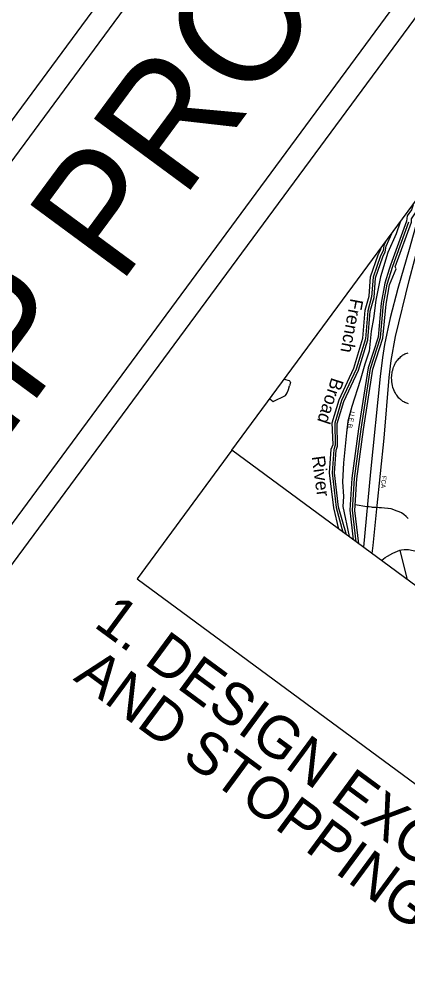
# Model space of a CAD drawing. Extents: x 945666 to 965748, y 644452 to 663300.
# Drawn here: x 951483 to 952293, y 657713 to 659710 of the extents above; entities that cross this region are included whole.
import ezdxf

# ---------------------------------------------------------------- set-up
doc = ezdxf.new("R2010")
doc.units = 0
for name, color, linetype in [('Exist Boundary Political Urban Extension UEB', 7, 'Continuous'), ('Exist Boundary Political Urban Extension UEB Label', 7, 'Continuous'), ('Exist Hydrographic Buffer Line', 7, 'Continuous'), ('Exist Hydrographic Creek Single Shore', 7, 'Continuous'), ('Exist Hydrographic Pond Under 1500 Sq Ft', 7, 'Continuous'), ('Exist Hydrographic River Shore', 7, 'Continuous'), ('Exist Hydrographic River Shore Label', 7, 'Continuous'), ('Exist Road Primary Interstate Divided Center Attributed', 7, 'Continuous'), ('Exist Road Primary US Label', 7, 'Continuous'), ('Exist Road Secondary Type 51 Attributed', 7, 'Continuous'), ('Old_Level_1', 7, 'Continuous'), ('Prop Terminator CELL', 7, 'Continuous'), ('Sheet Data Field CELL', 7, 'Continuous'), ('Sheet Title CELL', 7, 'Continuous')]:
    doc.layers.add(name, color=color, linetype=linetype)

msp = doc.modelspace()

# ---------------------------------------------------------------- linework, layer by layer
at = {"layer": 'Exist Boundary Political Urban Extension UEB'}
msp.add_lwpolyline([(952276.6, 659287.1), (952268.7, 659263.3), (952251.1, 659224.5), (952236, 659173.2), (952226.3, 659124.6), (952221.3, 659086.9), (952216.4, 659060.2), (952212.4, 659018.3), (952202.9, 658991.5), (952193.4, 658957.2), (952176.2, 658903), (952167.9, 658872.6), (952165.2, 658848.4), (952158.8, 658785.6), (952156.8, 658746.4), (952158.7, 658715.4), (952157.4, 658694.7), (952170.3, 658632.2), (952170.3, 658632.1)], dxfattribs=at)
at = {"layer": 'Exist Hydrographic Buffer Line'}
for points in [[(952303.7, 659323.8), (952300.7, 659313.2), (952291.7, 659300.3), (952289.8, 659289.2), (952256.4, 659197.7), (952253.9, 659189.6), (952244.7, 659160.5), (952237.2, 659118.3), (952230.7, 659047.9), (952209.9, 658984.1), (952190.2, 658857), (952176.2, 658754.1), (952172.3, 658687.5), (952179.2, 658625.5)], [(952184.9, 658621.3), (952177.4, 658687.2), (952181.4, 658753.4), (952195.3, 658856.2), (952214.9, 658982.5), (952235.9, 659046.8), (952242.4, 659117.5), (952249.5, 659158.5), (952261.3, 659195.9), (952295, 659288.3)], [(952165.2, 658635.9), (952148.5, 658693.8), (952140.1, 658764.9), (952143.6, 658812.4), (952146.6, 658820.6), (952145.9, 658868), (952159.7, 658913.6), (952189.8, 658979), (952209.3, 659042.5), (952214.4, 659101.9), (952222.4, 659130.5), (952225.6, 659171.5), (952240.6, 659215.4), (952245.9, 659225.3), (952248, 659237.5), (952259.5, 659264)], [(952245.7, 659245.3), (952242.9, 659238.8), (952241.4, 659227.8), (952235.8, 659217.4), (952220.5, 659172.5), (952217.4, 659132), (952209.2, 659102.8), (952204.3, 659044), (952185, 658981.1), (952154.9, 658915.5), (952140.7, 658868.7), (952141.7, 658822.4), (952138.5, 658813.5), (952134.9, 658764.8), (952143.4, 658692.9), (952157.7, 658641.4)]]:
    msp.add_lwpolyline(points, dxfattribs=at)
at = {"layer": 'Exist Hydrographic Creek Single Shore'}
msp.add_lwpolyline([(952293.8, 658669.9), (952289.3, 658674.2), (952284.5, 658677.9), (952279.7, 658681.4), (952274.5, 658683.6), (952268.8, 658686.1), (952263.6, 658688.2), (952257.8, 658689.8), (952251.5, 658690.6), (952250.9, 658690.7), (952244.5, 658691.5), (952237.8, 658691.8), (952232.8, 658691.8), (952226.3, 658692.8), (952223.3, 658692.7), (952219.5, 658693), (952217, 658693.5), (952212.4, 658694.2), (952207.4, 658694.4), (952183.3, 658698.2)], dxfattribs=at)
at = {"layer": 'Exist Hydrographic Pond Under 1500 Sq Ft'}
for points in [[(952005.2, 658919.1), (952005.5, 658918.9), (952012.1, 658913.4), (952037.7, 658926.4), (952039.6, 658928.4), (952041.7, 658931.5), (952042.1, 658932.9), (952044.1, 658938.6), (952046.4, 658946.6)], [(952035.3, 658959.9), (952045.6, 658957.7), (952047.3, 658956.2), (952048.5, 658953.4), (952046.4, 658946.6)]]:
    msp.add_lwpolyline(points, dxfattribs=at)
at = {"layer": 'Exist Hydrographic River Shore'}
for points in [[(952190.6, 658617.1), (952182.6, 658686.9), (952186.5, 658752.7), (952200.4, 658855.5), (952219.8, 658980.9), (952241, 659045.8), (952247.5, 659116.6), (952254.3, 659156.5), (952268.3, 659189.8), (952266.2, 659194.1), (952300.2, 659287.4), (952300.2, 659294.3), (952310.2, 659308.7), (952320.5, 659346), (952321.5, 659348.1)], [(952149, 658647.8), (952138.3, 658691.9), (952129.7, 658764.7), (952133.3, 658814.6), (952136.9, 658824.2), (952135.5, 658869.4), (952150, 658917.3), (952180.3, 658983.3), (952199.3, 659045.5), (952204.1, 659103.7), (952212.4, 659133.4), (952215.3, 659173.6), (952231.1, 659219.5), (952236.8, 659230.2), (952237.1, 659233.7)]]:
    msp.add_lwpolyline(points, dxfattribs=at)
at = {"layer": 'Exist Road Primary Interstate Divided Center Attributed'}
for points in [[(952218.3, 658596.7), (952220.4, 658613.7), (952228.1, 658689.9), (952243.2, 658837.5), (952254.1, 658963.6), (952258.3, 658998.8), (952267.2, 659049.2), (952295.8, 659166), (952342.5, 659343.9), (952356.2, 659395.1)], [(952336.7, 659368.6), (952330.6, 659347.6), (952312.2, 659290), (952295.5, 659230.6), (952272.3, 659149.4), (952256.2, 659087.8), (952244.1, 659032.4), (952239.9, 659005.6), (952235.5, 658965.7), (952215.3, 658767), (952200.4, 658609.9)]]:
    msp.add_lwpolyline(points, dxfattribs=at)
at = {"layer": 'Exist Road Secondary Type 51 Attributed'}
for points in [[(952275.8, 658603.7), (952279.8, 658604.7), (952285.3, 658605.6), (952289.6, 658605.4), (952294.1, 658605.5), (952313.7, 658601.3), (952333.2, 658596.5), (952350.3, 658594.3), (952360.2, 658596), (952363.5, 658598.5), (952370.2, 658602.9), (952382.7, 658611.9), (952388.7, 658615.1), (952397.7, 658619.2), (952404.8, 658620.7), (952411.3, 658621.6), (952422.2, 658622.6), (952450.3, 658623.5), (952473.9, 658624.4), (952488.3, 658624.4), (952501.8, 658624.2), (952514.1, 658623.5), (952521.7, 658623.1), (952538.8, 658621.2)], [(952237.9, 658582.3), (952238.5, 658582.9), (952245.5, 658588.4), (952250.3, 658591.7), (952261.2, 658597.6), (952275.8, 658603.7)], [(952275.8, 658603.7), (952290.8, 658544.9)], [(952290.8, 658544.9), (952289.2, 658544.4)], [(952290.8, 658544.9), (952291.4, 658542.8)]]:
    msp.add_lwpolyline(points, dxfattribs=at)
at = {"layer": 'Old_Level_1'}
for points in [[(953667.4, 661172.9), (956829.7, 658840.6), (955088.6, 656479.8), (951926.2, 658812.1)], [(951728.9, 658544.5), (954891.3, 656212.2), (955088.6, 656479.8), (951926.2, 658812.1)]]:
    msp.add_lwpolyline(points, close=True, dxfattribs=at)
at = {"layer": 'Prop Terminator CELL'}
msp.add_lwpolyline([(952294.3, 658908.8), (952292.5, 658909.3), (952290.5, 658909.9), (952288.3, 658910.8), (952286.2, 658911.8), (952284.4, 658912.7), (952282.5, 658913.9), (952280.9, 658915), (952279.3, 658916.2), (952277.9, 658917.5), (952276.2, 658918.9), (952274.2, 658920.9), (952272.7, 658922.6), (952271.2, 658924.6), (952269.6, 658926.7), (952268.1, 658929), (952266.3, 658932.2), (952265.2, 658934.5), (952263.5, 658938.3), (952261.8, 658943.2), (952260.8, 658947.2), (952260.1, 658950.3), (952259.5, 658955.1), (952259.2, 658958.2), (952259.1, 658963.4), (952259.2, 658967), (952259.4, 658969.5), (952260, 658973.5), (952260.4, 658975.9), (952261.2, 658979.3), (952262.1, 658982.3), (952263, 658985.1), (952263.7, 658986.8), (952265, 658989.7), (952266, 658991.8), (952267.4, 658994.4), (952269.2, 658997.1), (952270.9, 658999.5), (952272.4, 659001.5), (952274.3, 659003.6), (952276.5, 659005.7), (952278.5, 659007.5), (952280, 659008.7), (952282, 659010), (952284.3, 659011.5), (952286.7, 659012.7), (952288.8, 659013.6), (952291.2, 659014.5), (952293.4, 659015.1)], dxfattribs=at)
at = {"layer": 'Sheet Title CELL'}
for p, q in [((947649.9, 653481.5), (953704.1, 661690.4)), ((948788.2, 654940.7), (953744.3, 661660.7))]:
    msp.add_line(p, q, dxfattribs=at)
for points in [[(953331.4, 662027.4), (947217.8, 653738)], [(953331.4, 662027.4), (947217.8, 653738)], [(953342, 661957.4), (947287.8, 653748.6)]]:
    msp.add_lwpolyline(points, dxfattribs=at)

# ---------------------------------------------------------------- texts
at = {"layer": 'Exist Boundary Political Urban Extension UEB Label'}
msp.add_text('U.E.B.', height=9.8, rotation=260.1419, dxfattribs=at).set_placement((952173, 658894))
at = {"layer": 'Exist Hydrographic River Shore Label'}
for s, rotation, p in [('French', 259.1633, (952173.6, 659129.6)), ('Broad', 251.6495, (952134.1, 658965.1)), ('River', 277.622, (952092.5, 658798.8))]:
    msp.add_text(s, height=27.28, rotation=rotation, dxfattribs=at).set_placement(p)
at = {"layer": 'Exist Road Primary US Label'}
msp.add_text('FCA', height=9.38, rotation=264.5084, dxfattribs=at).set_placement((952239.1, 658759.3))
at = {"layer": 'Sheet Data Field CELL'}
for s, p in [('1. DESIGN EXCEPTIONS FOR VERTICAL CURVE K VALUE', (951636, 658446)), (' AND STOPPING SIGHT DISTANCE HAVE BEEN REQUESTED', (951567.9, 658353.7))]:
    msp.add_text(s, height=87.501, rotation=323.5908, dxfattribs=at).set_placement(p)
at = {"layer": 'Sheet Title CELL'}
msp.add_text('TIP PROJECT:', height=250, rotation=53.5908, dxfattribs=at).set_placement((951327.6, 658659.9))

doc.saveas('drawing.dxf')
